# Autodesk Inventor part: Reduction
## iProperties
Shininess: 64.0
Length Units: 11269
Angle Units: 11279
Time Units: 11290
Mass Units: 11283
Length Display Precision: 3
Angle Display Precision: 2
Compacted: True
Part Number: Reduction
Document SubType Name: Modeling
Created: 2008-02
Material: Par défaut
Designer: Pascal
Density: 0.0
Volumn: 0.0
Area: 0.0
PropertySet Name: Model Information
Control State: 0
Master: False
Checked Out: False
DESIGNATION: pièce
Author: Pascal
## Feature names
1. Lissage2
2. Lissage3
3. Extrusion1
